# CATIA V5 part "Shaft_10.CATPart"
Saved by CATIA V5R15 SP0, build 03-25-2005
Part number: Shaft_10
Bounding box of the stored display mesh (mm): x -23.8 to 23.8, y -23.8 to 23.8, z 0 to 790
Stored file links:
  E:\#01 CATIA Lecture Materials\#06 DMU\#11 DMU Page01 KIN EX11\Shaft_10.CATPart
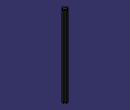
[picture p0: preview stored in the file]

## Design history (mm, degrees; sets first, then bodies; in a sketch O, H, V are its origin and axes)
Body1 (main body)
  Sketch1 on xy-plane, origin (0, 0, 0), H (1, 0, 0), V (0, 1, 0)
    arc A1 centre (0, 0) radius 23.8 from (21.9289, -9.25) to (21.9289, 9.25) ccw
    line L1 (-21.9289, 9.25) -> (-9.25, 9.25)
    line L2 (21.9289, -9.25) -> (9.25, -9.25)
    line L3 (9.25, 21.9289) -> (9.25, 9.25)
    line L4 (-9.25, -21.9289) -> (-9.25, -9.25)
    point P4 (-9.25, -21.9289)
    arc A2 centre (0, 0) radius 23.8 from (-9.25, -21.9289) to (9.25, -21.9289) ccw
    point P6 (-21.9289, 9.25)
    arc A3 centre (0, 0) radius 23.8 from (-21.9289, 9.25) to (-21.9289, -9.25) ccw
    point P8 (9.25, 21.9289)
    arc A4 centre (0, 0) radius 23.8 from (9.25, 21.9289) to (-9.25, 21.9289) ccw
    point P9 (-9.25, 9.25)
    line L5 (9.25, 9.25) -> (21.9289, 9.25)
    line L6 (9.25, -9.25) -> (9.25, -21.9289)
    line L7 (-9.25, 9.25) -> (-9.25, 21.9289)
    point P12 (-9.25, -9.25)
    line L8 (-9.25, -9.25) -> (-21.9289, -9.25)
    radius A1 = 23.8
    distance L1 L2 = 18.5
    distance H L1 = 9.25
    distance L3 L4 = 18.5
    distance V L3 = 9.25
    horizontal: L1 H, L2 H, L5 H, L8 H
    vertical: L3 V, L4 V, L6 V, L7 V
    coincidence: A1 P4, A1 A2, A1 P6, A1 A3, A1 P8, A1 A4, L4 P9, L1 L5, L3 L6, L2 P12, L4 L7, L2 L8
  Pad1: profile Sketch1, direction (0, 0, 1), length 790
  Fillet1: radius 2, on edge [face of Pad1 | face of Pad1] (x4)
  Fillet2: radius 2, on face of Pad1 (x2)
  Fillet3: radius 2, on edge [face of Pad1 from Sketch1.A4 | face of Pad1 from Sketch1.L3]; edge [face of Pad1 from Sketch1.L5 | face of Pad1 from Sketch1.A1]; edge [face of Pad1 from Sketch1.A1 | face of Pad1 from Sketch1.L2]; edge [face of Pad1 from Sketch1.L6 | face of Pad1 from Sketch1.A2]; edge [face of Pad1 from Sketch1.A2 | face of Pad1 from Sketch1.L4]; edge [face of Pad1 from Sketch1.L8 | face of Pad1 from Sketch1.A3]; edge [face of Pad1 from Sketch1.L7 | face of Pad1 from Sketch1.A4]; edge [face of Pad1 from Sketch1.A3 | face of Pad1 from Sketch1.L1]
